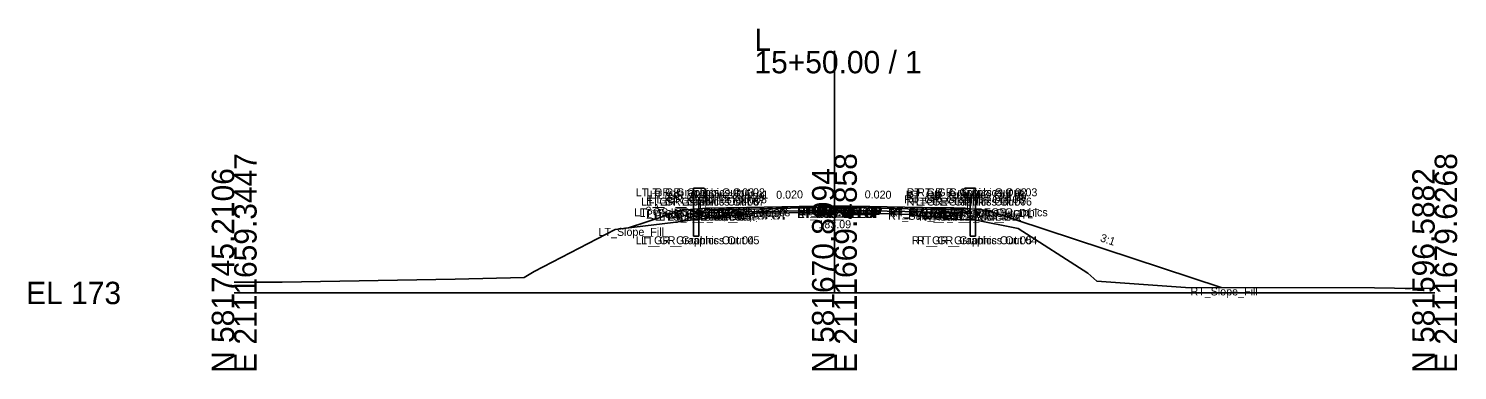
# Model space of a CAD drawing. Extents: x -26 to 3453, y -333 to 9539.
# Drawn here: x -25.7 to 152.8, y 5990.3 to 6033.1 of the extents above; entities that cross this region are included whole.
import ezdxf

# ---------------------------------------------------------------- set-up
doc = ezdxf.new("R2010")
doc.units = 0
for name, color, linetype in [('Default', 7, 'Continuous'), ('Exist Cross Section Cell', 7, 'Continuous'), ('Exist XS Center Line Elevation Label', 7, 'Continuous'), ('Exist XS Ground Line', 7, 'Continuous'), ('Prop CMT Guardrail Graphics', 7, 'Continuous'), ('Prop CMT Pvmt Course 1', 7, 'Continuous'), ('Prop CMT Pvmt Course 2', 7, 'Continuous'), ('Prop CMT Pvmt Course 3', 7, 'Continuous'), ('Prop CMT Pvmt Surface', 7, 'Continuous'), ('Prop CMT Pvmt Surface Shoulder', 7, 'Continuous'), ('Prop CMT Shld Paved Course 1', 7, 'Continuous'), ('Prop CMT Shld Paved Course 2', 7, 'Continuous'), ('Prop CMT Shld Paved Course 3', 7, 'Continuous'), ('Prop CMT Slope Grass', 7, 'Continuous'), ('Prop CMT Subgrade Earthwork', 7, 'Continuous'), ('Prop XS SE Text', 7, 'Continuous'), ('Prop XS Side Slope Text', 7, 'Continuous'), ('Scratch_Level_0', 7, 'Continuous')]:
    doc.layers.add(name, color=color, linetype=linetype)

msp = doc.modelspace()

# ---------------------------------------------------------------- linework, layer by layer
at = {"layer": 'Exist Cross Section Cell'}
for p, q in [((75, 6000), (75, 6030.27)), ((0, 6000), (75, 6000)), ((75, 6000), (150, 6000))]:
    msp.add_line(p, q, dxfattribs=at)
at = {"layer": 'Exist XS Ground Line'}
for p, q in [((57.93, 6009.23), (65.25, 6009.99)), ((65.25, 6009.99), (73.4, 6010.07)), ((73.4, 6010.07), (74.83, 6010.09)), ((74.83, 6010.09), (83.25, 6009.87)), ((83.25, 6009.87), (84.67, 6009.83)), ((84.67, 6009.83), (90.41, 6009.2)), ((37.49, 6002.67), (47.6, 6007.93)), ((47.6, 6007.93), (54.83, 6008.81)), ((54.83, 6008.81), (57.93, 6009.23)), ((90.41, 6009.2), (92.5, 6009.13)), ((92.5, 6009.13), (97.95, 6008.08)), ((97.95, 6008.08), (106.66, 6002.47)), ((36.24, 6001.94), (37.49, 6002.67)), ((106.66, 6002.47), (107.79, 6001.47)), ((0, 6001.36), (3.26, 6001.37)), ((3.26, 6001.37), (5.98, 6001.35)), ((5.98, 6001.35), (27.59, 6001.71)), ((27.59, 6001.71), (36.24, 6001.94)), ((107.79, 6001.47), (118.87, 6000.69)), ((118.87, 6000.69), (142.48, 6000.65)), ((142.48, 6000.65), (144.99, 6000.58)), ((144.99, 6000.58), (146.31, 6000.57)), ((146.31, 6000.57), (146.96, 6000.56)), ((146.96, 6000.56), (150, 6000.58))]:
    msp.add_line(p, q, dxfattribs=at)
at = {"layer": 'Prop CMT Guardrail Graphics'}
for points in [[(57.39, 6007.09), (57.39, 6013.09)], [(57.39, 6013.09), (58.72, 6013.09), (58.99, 6012.8)], [(92.61, 6013.09), (91.28, 6013.09), (91.01, 6012.8)], [(92.61, 6007.09), (92.61, 6013.09)], [(58.99, 6012.22), (58.72, 6011.93), (58.05, 6011.93)], [(58.05, 6011.93), (58.05, 6007.09)], [(58.99, 6012.8), (58.72, 6012.51)], [(58.72, 6012.51), (58.99, 6012.22)], [(91.01, 6012.8), (91.28, 6012.51)], [(91.28, 6012.51), (91.01, 6012.22)], [(91.01, 6012.22), (91.28, 6011.93), (91.95, 6011.93)], [(91.95, 6011.93), (91.95, 6007.09)], [(58.05, 6007.09), (57.39, 6007.09)], [(91.95, 6007.09), (92.61, 6007.09)]]:
    msp.add_lwpolyline(points, dxfattribs=at)
at = {"layer": 'Prop CMT Pvmt Course 1'}
for points in [[(75, 6010.91), (64, 6010.69)], [(64, 6010.49), (75, 6010.71)], [(64, 6010.69), (64, 6010.49)], [(75, 6010.71), (75, 6010.91)], [(75, 6010.91), (86, 6010.69)], [(75, 6010.71), (75, 6010.91)], [(86, 6010.49), (75, 6010.71)], [(86, 6010.69), (86, 6010.49)]]:
    msp.add_lwpolyline(points, dxfattribs=at)
msp.add_lwpolyline([(75, 6010.71), (75, 6010.79), (75, 6010.79), (75, 6010.71)], close=True, dxfattribs=at)
msp.add_lwpolyline([(75, 6010.71), (75, 6010.79), (75, 6010.79), (75, 6010.71)], close=True, dxfattribs=at)
at = {"layer": 'Prop CMT Pvmt Course 2'}
for points in [[(75, 6010.71), (64, 6010.49)], [(64, 6010.49), (64, 6010.15)], [(64, 6010.15), (75, 6010.37)], [(75, 6010.37), (75, 6010.71)], [(75, 6010.37), (75, 6010.71)], [(75, 6010.71), (86, 6010.49)], [(86, 6010.15), (75, 6010.37)], [(86, 6010.49), (86, 6010.15)]]:
    msp.add_lwpolyline(points, dxfattribs=at)
at = {"layer": 'Prop CMT Pvmt Course 3'}
for points in [[(75, 6010.37), (64, 6010.15)], [(64, 6010.15), (75, 6010.37)], [(64, 6010.15), (64, 6010.15)], [(75, 6010.37), (75, 6010.37)], [(75, 6010.37), (86, 6010.15)], [(86, 6010.15), (75, 6010.37)], [(75, 6010.37), (75, 6010.37)], [(86, 6010.15), (86, 6010.15)]]:
    msp.add_lwpolyline(points, dxfattribs=at)
at = {"layer": 'Prop CMT Pvmt Surface'}
for points in [[(75, 6010.91), (64, 6010.69)], [(75, 6010.91), (86, 6010.69)]]:
    msp.add_lwpolyline(points, dxfattribs=at)
at = {"layer": 'Prop CMT Pvmt Surface Shoulder'}
for points in [[(64, 6010.69), (59, 6010.59)], [(86, 6010.69), (91, 6010.59)]]:
    msp.add_lwpolyline(points, dxfattribs=at)
at = {"layer": 'Prop CMT Shld Paved Course 1'}
for points in [[(64, 6010.69), (59, 6010.59), (58.79, 6010.38)], [(58.79, 6010.38), (64, 6010.49)], [(64, 6010.49), (64, 6010.69)], [(86, 6010.69), (91, 6010.59), (91.21, 6010.38)], [(86, 6010.49), (86, 6010.69)], [(91.21, 6010.38), (86, 6010.49)]]:
    msp.add_lwpolyline(points, dxfattribs=at)
at = {"layer": 'Prop CMT Shld Paved Course 2'}
for points in [[(64, 6010.49), (58.79, 6010.38), (58.45, 6010.04)], [(58.45, 6010.04), (64, 6010.15)], [(64, 6010.15), (64, 6010.49)], [(86, 6010.49), (91.21, 6010.38), (91.55, 6010.04)], [(86, 6010.15), (86, 6010.49)], [(91.55, 6010.04), (86, 6010.15)]]:
    msp.add_lwpolyline(points, dxfattribs=at)
at = {"layer": 'Prop CMT Shld Paved Course 3'}
for points in [[(64, 6010.15), (58.45, 6010.04)], [(58.45, 6010.04), (64, 6010.15)], [(58.45, 6010.04), (58.45, 6010.04), (58.45, 6010.04)], [(64, 6010.15), (64, 6010.15)], [(86, 6010.15), (91.55, 6010.04)], [(91.55, 6010.04), (86, 6010.15)], [(86, 6010.15), (86, 6010.15)], [(91.55, 6010.04), (91.55, 6010.04), (91.55, 6010.04)]]:
    msp.add_lwpolyline(points, dxfattribs=at)
at = {"layer": 'Prop CMT Slope Grass'}
for p, q in [((59, 6010.59), (56, 6010.35)), ((91, 6010.59), (91.01, 6010.59))]:
    msp.add_line(p, q, dxfattribs=at)
for points in [[(56, 6010.35), (49.28, 6008.14)], [(59, 6010.59), (58.99, 6010.59)], [(91.01, 6010.59), (94, 6010.35)], [(94, 6010.35), (123.3, 6000.69)]]:
    msp.add_lwpolyline(points, dxfattribs=at)
at = {"layer": 'Prop CMT Subgrade Earthwork'}
for points in [[(58.45, 6010.04), (57.98, 6010.51)], [(64, 6010.15), (58.45, 6010.04)], [(75, 6010.37), (64, 6010.15)], [(75, 6010.37), (86, 6010.15)], [(86, 6010.15), (91.55, 6010.04)], [(91.55, 6010.04), (92.02, 6010.51)]]:
    msp.add_lwpolyline(points, dxfattribs=at)

# ---------------------------------------------------------------- texts
at = {"layer": 'Default'}
msp.add_text('-', height=0.0001, dxfattribs=at).set_placement((0, 6000))
at = {"layer": 'Exist Cross Section Cell'}
for s, p in [('L', (65, 6030.27)), ('15+50.00 / 1', (65, 6027.47)), ('EL 173', (-26, 5998.6))]:
    msp.add_text(s, height=2.8, dxfattribs=at).set_placement(p)
for s, p in [('E 2111659.3447', (2.8, 5990)), ('E 2111669.4858', (77.8, 5990)), ('E 2111679.6268', (152.8, 5990)), ('N 581745.2106', (0, 5990)), ('N 581670.8994', (75, 5990)), ('N 581596.5882', (150, 5990))]:
    msp.add_text(s, height=2.8, rotation=90, dxfattribs=at).set_placement(p)
at = {"layer": 'Exist XS Center Line Elevation Label'}
msp.add_text('183.09', height=1, dxfattribs=at).set_placement((72.99, 6008.09))
at = {"layer": 'Prop XS SE Text'}
for rotation, p in [(1.1458, (67.73, 6011.77)), (358.8542, (78.77, 6011.84))]:
    msp.add_text('0.020', height=1, rotation=rotation, dxfattribs=at).set_placement(p)
at = {"layer": 'Prop XS Side Slope Text'}
for rotation, p in [(18.2629, (51.65, 6009.71)), (341.7371, (108.13, 6006.48))]:
    msp.add_text('3:1', height=1, rotation=rotation, dxfattribs=at).set_placement(p)
at = {"layer": 'Scratch_Level_0'}
for s, p in [('LT_GR_Graphics Out 03', (50.17, 6012.09)), ('LT_GR_Graphics Out 02', (51.52, 6012.09)), ('RT_GR_Graphics Out 02', (84.02, 6012.09)), ('RT_GR_Graphics Out 03', (85.34, 6012.09)), ('LT_GR_Graphics Out 06', (50.83, 6010.93)), ('LT_GR_Graphics Out 07', (51.48, 6010.93)), ('LT_GR_Graphics Out 09', (51.49, 6011.51)), ('LT_GR_Graphics Out 08', (51.76, 6011.22)), ('LT_GR_Graphics Out 01', (51.94, 6011.8)), ('RT_GR_Graphics Out 08', (83.72, 6011.22)), ('RT_GR_Graphics Out 01', (83.9, 6011.8)), ('RT_GR_Graphics Out 07', (83.98, 6010.93)), ('RT_GR_Graphics Out 09', (84, 6011.51)), ('RT_GR_Graphics Out 06', (84.66, 6010.93)), ('LT_GS_OS_GR_Face_Graphics', (49.99, 6009.59)), ('LT_Sub_Trench_Out_DLT', (50.63, 6009.51)), ('LT_GS_OS_CTL', (51.46, 6009.35)), ('LT_Sub_Trench_Out', (52.56, 6009.04)), ('LT_PS3_Shelf_Out', (53.1, 6009.04)), ('LT_PS3_OEOP', (54.23, 6009.04)), ('LT_PS2_OEOP', (54.57, 6009.38)), ('LT_PS1_OEOP', (54.91, 6009.59)), ('LT_PV2_OEOT', (59.75, 6009.49)), ('LT_PV3_OEOT', (59.75, 6009.15)), ('LT_Sub_OEOT', (59.77, 6009.15)), ('LT_PV1_OEOT', (59.87, 6009.69)), ('RT_PV2_OEEOP', (70.33, 6009.71)), ('RT_PV3_OEEOP', (70.33, 6009.37)), ('RT_Sub_OEEOP', (70.36, 6009.37)), ('LT_PV2_OEEOP', (70.39, 6009.71)), ('LT_PV3_OEEOP', (70.39, 6009.37)), ('LT_Sub_OEEOP', (70.42, 6009.37)), ('RT_PV1_OEEOP', (70.45, 6009.79)), ('LT_PV1_OEEOP', (70.51, 6009.79)), ('RT_PV2_IEEOP', (70.71, 6009.71)), ('LT_PV2_IEEOP', (70.77, 6009.71)), ('RT_PV1_IEEOP', (70.83, 6009.79)), ('LT_PV1_IEEOP', (70.89, 6009.79)), ('PV2_PGL', (72.35, 6009.71)), ('PV1_PGL', (72.47, 6009.91)), ('RT_PV2_OEOT', (81.69, 6009.49)), ('RT_PV3_OEOT', (81.69, 6009.15)), ('RT_Sub_OEOT', (81.71, 6009.15)), ('RT_PV1_OEOT', (81.81, 6009.69)), ('RT_GS_OS_GR_Face_Graphics', (81.95, 6009.59)), ('RT_Sub_Trench_Out_DLT', (84.61, 6009.51)), ('RT_Sub_Trench_Out', (85.6, 6009.04)), ('RT_PS3_Shelf_Out', (86.15, 6009.04)), ('RT_PS1_OEOP', (86.85, 6009.59)), ('RT_PS2_OEOP', (86.94, 6009.38)), ('RT_PS3_OEOP', (87.28, 6009.04)), ('RT_GS_OS_CTL', (89.4, 6009.35)), ('LT_Slope_Fill', (45.52, 6007.14)), ('LT_GR_Graphics Out 04', (50.16, 6006.09)), ('LT_GR_Graphics Out 05', (50.83, 6006.09)), ('RT_GR_Graphics Out 05', (84.67, 6006.09)), ('RT_GR_Graphics Out 04', (85.32, 6006.09)), ('RT_Slope_Fill', (119.48, 5999.69))]:
    msp.add_text(s, height=1, dxfattribs=at).set_placement(p)

doc.saveas('drawing.dxf')
